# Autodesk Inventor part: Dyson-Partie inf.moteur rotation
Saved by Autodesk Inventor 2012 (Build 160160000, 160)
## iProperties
Created: 2012-11
Part Number: Dyson-Partie inf.moteur rotation
Material: Default
Document SubType Name: Modeling
Designer: Administrateur
Density: 1 g/cm^3
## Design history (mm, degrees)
node "Dyson-Partie inf.moteur rotation1"
node "Dyson-Partie inf.moteur rotation"
node "Dyson-Partie inf.moteur rotation_1"
node "Base1"
node "Base2"
